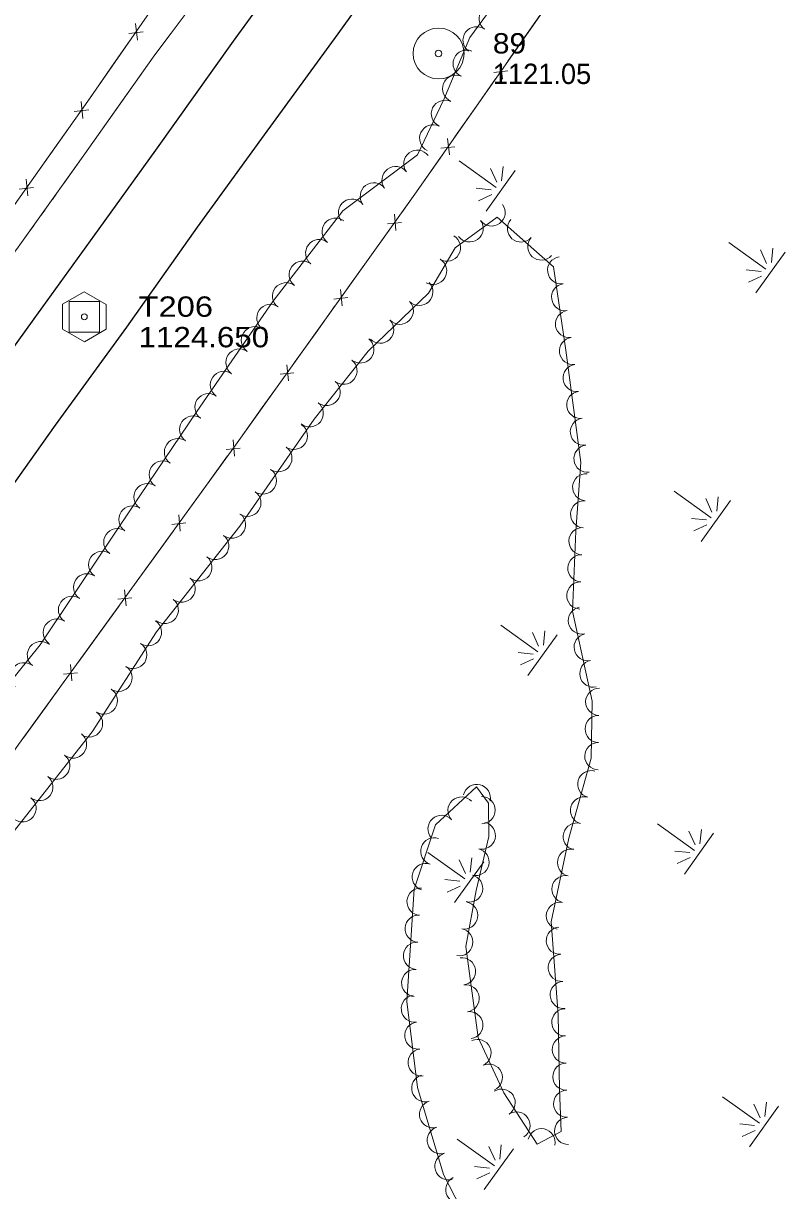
# Model space of a CAD drawing. Extents: x 297327 to 299792, y 46897 to 49095.
# Drawn here: x 298564.4 to 298789.7, y 47500 to 47844.1 of the extents above; entities that cross this region are included whole.
import ezdxf

# ---------------------------------------------------------------- set-up
doc = ezdxf.new("R2010")
doc.units = 0
doc.header["$LTSCALE"] = 2.4
for name, color, linetype, lineweight in [('11', 7, 'Continuous', 25), ('15', 7, 'Continuous', 13), ('18', 7, 'Continuous', 13), ('19', 7, 'Continuous', 13), ('5', 7, 'Continuous', 13), ('6', 7, 'Continuous', 13)]:
    doc.layers.add(name, color=color, linetype=linetype, lineweight=lineweight)

msp = doc.modelspace()

# ---------------------------------------------------------------- linework, layer by layer
at = {"layer": '11'}
for points in [[(298388.911, 47508.371), (298406.106, 47532.273), (298427.668, 47562.116), (298449.984, 47593.336), (298470.117, 47621.114), (298489.839, 47648.885), (298509.891, 47677.16), (298529.03, 47703.573), (298549.632, 47732.257), (298567.565, 47756.994), (298586.721, 47783.539), (298603.426, 47806.737), (298626.295, 47838.881), (298646.065, 47866.048), (298669.869, 47899.268), (298693.507, 47931.962), (298714.623, 47961.338), (298735.651, 47990.506), (298754.046, 48016.186), (298773.947, 48043.937), (298797.872, 48077.411)], [(298407.334, 47494.128), (298425.338, 47519.051), (298445.675, 47547.22), (298466.267, 47575.884), (298487.159, 47604.501), (298507.887, 47633.716), (298528.686, 47661.791), (298551.246, 47693.855), (298573.871, 47725.614), (298594.877, 47754.505), (298615.749, 47784.013), (298635.436, 47811.25), (298657.227, 47840.959), (298677.914, 47869.928), (298700.338, 47901.145), (298719.301, 47927.484), (298741.917, 47959.101), (298761.856, 47986.895), (298781.415, 48014.255), (298799.539, 48039.023)]]:
    msp.add_lwpolyline(points, dxfattribs=at)
at = {"layer": '15'}
for p, q in [((298713.623, 47842.044), (298719.209, 47850.028)), ((298595.434, 47841.121), (298599.664, 47841.611)), ((298598.015, 47839.119), (298597.473, 47844.055)), ((298707.271, 47832.965), (298713.623, 47842.044)), ((298590.185, 47830.923), (298595.91, 47839.159)), ((298583.675, 47821.559), (298590.185, 47830.923)), ((298705.624, 47827.642), (298705.112, 47832.44)), ((298697.992, 47819.703), (298703.578, 47827.687)), ((298703.122, 47829.595), (298707.233, 47830.058)), ((298581.957, 47816.082), (298581.463, 47821.024)), ((298579.395, 47818.11), (298583.63, 47818.558)), ((298691.64, 47810.624), (298697.992, 47819.703)), ((298574.048, 47807.963), (298579.852, 47816.143)), ((298689.993, 47805.301), (298689.481, 47810.099)), ((298567.448, 47798.662), (298574.048, 47807.963)), ((298687.491, 47807.254), (298691.602, 47807.717)), ((298682.361, 47797.362), (298687.948, 47805.346)), ((298565.716, 47793.194), (298565.222, 47798.136)), ((298563.155, 47795.222), (298567.39, 47795.671)), ((298674.252, 47783.016), (298673.789, 47787.819)), ((298666.54, 47775.155), (298672.207, 47783.082)), ((298671.77, 47784.995), (298675.886, 47785.416)), ((298660.096, 47766.142), (298666.54, 47775.155)), ((298658.394, 47760.836), (298657.931, 47765.639)), ((298655.912, 47762.815), (298660.028, 47763.236)), ((298650.682, 47752.975), (298656.349, 47760.902)), ((298644.238, 47743.962), (298650.682, 47752.975)), ((298642.536, 47738.655), (298642.073, 47743.458)), ((298634.824, 47730.795), (298640.491, 47738.722)), ((298640.054, 47740.634), (298644.17, 47741.055)), ((298628.38, 47721.782), (298634.824, 47730.795)), ((298626.657, 47716.476), (298626.225, 47721.282)), ((298624.188, 47718.471), (298628.307, 47718.866)), ((298618.896, 47708.664), (298624.613, 47716.556)), ((298612.395, 47699.692), (298618.896, 47708.664)), ((298608.191, 47696.391), (298612.309, 47696.786)), ((298610.66, 47694.396), (298610.227, 47699.202)), ((298602.898, 47686.584), (298608.616, 47694.475)), ((298596.398, 47677.612), (298602.898, 47686.584)), ((298594.663, 47672.316), (298594.23, 47677.122)), ((298586.901, 47664.504), (298592.618, 47672.395)), ((298592.193, 47674.311), (298596.312, 47674.706)), ((298580.401, 47655.532), (298586.901, 47664.504)), ((298576.196, 47652.231), (298580.315, 47652.626)), ((298578.665, 47650.236), (298578.233, 47655.042)), ((298570.904, 47642.424), (298576.621, 47650.315)), ((298564.403, 47633.452), (298570.904, 47642.424))]:
    msp.add_line(p, q, dxfattribs=at)
for points in [[(298401.584, 47586.723), (298448.177, 47641.585), (298499.253, 47707.169), (298540.716, 47760.989), (298582.688, 47820.139), (298614.369, 47865.714), (298666.991, 47942.604), (298701.551, 47994.305), (298740.687, 48054.857), (298758.699, 48081.865), (298762.651, 48090.8), (298770.821, 48171.221)], [(298443.923, 47465.07), (298477.895, 47511.728), (298522.34, 47573.628), (298562.948, 47631.443), (298626.887, 47719.694), (298679.84, 47793.758), (298726.071, 47859.836), (298761.348, 47908.474)], [(298675.954, 47788.323), (298679.84, 47793.758), (298682.361, 47797.362)]]:
    msp.add_lwpolyline(points, dxfattribs=at)
at = {"layer": '18'}
for points in [[(298719.368, 47871.608), (298696.039, 47839.957), (298688.394, 47821.676), (298680.555, 47805.336), (298658.55, 47788.85), (298637.979, 47762.048), (298615.485, 47729.631), (298598.69, 47704.808), (298569.292, 47660.886), (298549.381, 47636.177)], [(298556.506, 47599.639), (298584.636, 47635.187), (298603.65, 47664.651), (298628.23, 47695.868), (298650.098, 47727.362), (298666.016, 47747.42), (298683.804, 47764.566), (298691.685, 47777.925), (298704.127, 47786.973), (298720.677, 47772.317), (298724.316, 47747.748), (298728.759, 47714.572), (298727.272, 47694.382), (298726.322, 47670.821), (298732.072, 47644.291), (298731.799, 47627.438), (298725.25, 47603.865), (298720.052, 47579.21), (298722.044, 47551.803), (298722.477, 47529.92), (298722.927, 47517.394), (298715.867, 47513.676), (298706.006, 47528.837), (298698.504, 47545.108), (298694.811, 47571.896), (298697.857, 47588.405), (298701.652, 47604.341), (298701.57, 47614.18), (298698.039, 47619.002), (298685.929, 47607.838), (298679.626, 47588.809), (298677.438, 47555.722), (298680.627, 47530.368), (298688.247, 47504.735), (298696.782, 47488.144)]]:
    msp.add_lwpolyline(points, dxfattribs=at)
for centre, start, end in [((298702.764, 47845.549), 53.61485, 233.59953), ((298698.013, 47839.103), 53.61485, 233.59953), ((298695.07, 47832.208), 67.31328, 247.29796), ((298691.981, 47824.82), 67.31328, 247.29796), ((298688.673, 47817.413), 64.37863, 244.36331), ((298685.21, 47810.194), 64.37863, 244.36331), ((298680.52, 47802.691), 36.84797, 216.83265), ((298674.112, 47797.89), 36.84797, 216.83265), ((298667.703, 47793.089), 36.84797, 216.83265), ((298661.295, 47788.288), 36.84797, 216.83265), ((298702.446, 47788.342), 216.03284, 36.01752), ((298656.47, 47782.697), 52.5008, 232.48548), ((298695.97, 47783.632), 216.03284, 36.01752), ((298711.096, 47783.601), 138.48088, 318.46556), ((298651.594, 47776.345), 52.5008, 232.48548), ((298689.278, 47777.969), 239.46963, 59.45431), ((298717.09, 47778.292), 138.48088, 318.46556), ((298646.719, 47769.993), 52.5008, 232.48548), ((298685.209, 47771.073), 239.46963, 59.45431), ((298722.949, 47771.278), 98.43269, 278.41736), ((298641.844, 47763.641), 52.5008, 232.48548), ((298681.134, 47764.903), 223.95482, 43.9395), ((298724.123, 47763.357), 98.43269, 278.41736), ((298675.369, 47759.346), 223.95482, 43.9395), ((298637.198, 47757.247), 55.25107, 235.23574), ((298725.296, 47755.436), 98.43269, 278.41736), ((298669.604, 47753.789), 223.95482, 43.9395), ((298632.633, 47750.668), 55.25107, 235.23574), ((298628.068, 47744.089), 55.25107, 235.23574), ((298663.75, 47747.936), 231.5722, 51.55687), ((298726.466, 47747.486), 97.63545, 277.62013), ((298658.773, 47741.664), 231.5722, 51.55687), ((298623.504, 47737.511), 55.25107, 235.23574), ((298727.528, 47739.549), 97.63545, 277.62013), ((298653.795, 47735.392), 231.5722, 51.55687), ((298618.939, 47730.932), 55.25107, 235.23574), ((298728.591, 47731.613), 97.63545, 277.62013), ((298648.817, 47729.12), 231.5722, 51.55687), ((298614.436, 47724.341), 55.92576, 235.91044), ((298729.654, 47723.677), 97.63545, 277.62013), ((298644.141, 47722.457), 235.23331, 55.21799), ((298609.949, 47717.709), 55.92576, 235.91044), ((298639.574, 47715.88), 235.23331, 55.21799), ((298730.717, 47715.74), 97.63545, 277.62013), ((298605.462, 47711.077), 55.92576, 235.91044), ((298635.007, 47709.303), 235.23331, 55.21799), ((298730.327, 47707.328), 85.79541, 265.78009), ((298600.975, 47704.445), 55.92576, 235.91044), ((298630.44, 47702.726), 235.23331, 55.21799), ((298729.739, 47699.342), 85.79541, 265.78009), ((298596.523, 47697.802), 56.21236, 236.19704), ((298625.894, 47696.289), 231.79107, 51.77574), ((298592.069, 47691.148), 56.21236, 236.19704), ((298620.941, 47689.998), 231.79107, 51.77574), ((298729.25, 47691.421), 87.6987, 267.68338), ((298587.615, 47684.494), 56.21236, 236.19704), ((298615.987, 47683.707), 231.79107, 51.77574), ((298728.927, 47683.42), 87.6987, 267.68338), ((298583.161, 47677.84), 56.21236, 236.19704), ((298611.034, 47677.416), 231.79107, 51.77574), ((298728.605, 47675.419), 87.6987, 267.68338), ((298578.707, 47671.185), 56.21236, 236.19704), ((298606.08, 47671.125), 231.79107, 51.77574), ((298729.074, 47668.02), 102.23657, 282.22124), ((298574.254, 47664.531), 56.21236, 236.19704), ((298601.121, 47664.596), 237.1723, 57.15698), ((298730.77, 47660.194), 102.23657, 282.22124), ((298569.532, 47657.844), 51.14511, 231.12979), ((298596.779, 47657.868), 237.1723, 57.15698), ((298564.508, 47651.609), 51.14511, 231.12979), ((298732.466, 47652.368), 102.23657, 282.22124), ((298592.437, 47651.14), 237.1723, 57.15698), ((298588.095, 47644.413), 237.1723, 57.15698), ((298734.164, 47644.061), 89.07961, 269.06429), ((298583.754, 47637.685), 237.1723, 57.15698), ((298734.035, 47636.054), 89.07961, 269.06429), ((298579.029, 47631.479), 231.65223, 51.63691), ((298733.905, 47628.048), 89.07961, 269.06429), ((298574.06, 47625.2), 231.65223, 51.63691), ((298569.092, 47618.921), 231.65223, 51.63691), ((298731.847, 47619.783), 74.48142, 254.4661), ((298698.089, 47615.734), 346.22181, 166.20649), ((298564.123, 47612.642), 231.65223, 51.63691), ((298693.577, 47612.038), 42.68009, 222.66476), ((298699.491, 47612.125), 270.48516, 90.46984), ((298729.704, 47612.068), 74.48142, 254.4661), ((298687.69, 47606.611), 42.68009, 222.66476), ((298699.566, 47604.627), 256.61273, 76.59741), ((298727.561, 47604.353), 74.48142, 254.4661), ((298685.546, 47600.017), 71.68117, 251.66585), ((298697.711, 47596.837), 256.61273, 76.59741), ((298725.873, 47596.663), 78.10237, 258.08705), ((298683.029, 47592.416), 71.68117, 251.66585), ((298695.856, 47589.048), 256.61273, 76.59741), ((298724.221, 47588.828), 78.10237, 258.08705), ((298681.485, 47585.165), 86.22428, 266.20895), ((298694.373, 47581.07), 259.55384, 79.53852), ((298722.57, 47580.993), 78.10237, 258.08705), ((298680.957, 47577.176), 86.22428, 266.20895), ((298692.92, 47573.196), 259.55384, 79.53852), ((298722.559, 47573.633), 94.16473, 274.14941), ((298680.429, 47569.186), 86.22428, 266.20895), ((298723.139, 47565.647), 94.16473, 274.14941), ((298693.701, 47564.604), 277.85699, 97.84167), ((298679.9, 47561.196), 86.22428, 266.20895), ((298694.794, 47556.672), 277.85699, 97.84167), ((298723.719, 47557.661), 94.16473, 274.14941), ((298679.815, 47553.619), 97.17662, 277.1613), ((298695.888, 47548.74), 277.85699, 97.84167), ((298724.185, 47549.559), 91.14123, 271.12591), ((298680.814, 47545.675), 97.17662, 277.1613), ((298724.343, 47541.553), 91.14123, 271.12591), ((298681.813, 47537.73), 97.17662, 277.1613), ((298698.298, 47540.55), 294.76047, 114.74514), ((298701.65, 47533.279), 294.76047, 114.74514), ((298724.501, 47533.548), 91.14123, 271.12591), ((298682.878, 47530.15), 106.56346, 286.54813), ((298705.421, 47525.892), 303.0484, 123.03307), ((298724.73, 47525.578), 92.06514, 272.04982), ((298685.16, 47522.475), 106.56346, 286.54813), ((298709.787, 47519.18), 303.0484, 123.03307), ((298725.018, 47517.576), 92.06514, 272.04982), ((298687.442, 47514.799), 106.56346, 286.54813), ((298717.147, 47514.242), 347.78025, 167.76493), ((298689.723, 47507.124), 106.56346, 286.54813), ((298692.918, 47500.236), 117.23056, 297.21524)]:
    msp.add_arc(centre, 4.004, start, end, dxfattribs=at)
at = {"layer": '19'}
for p, q in [((298692.862, 47803.505), (298703.775, 47795.695)), ((298700.795, 47788.697), (298709.406, 47800.728)), ((298703.981, 47797.306), (298702.13, 47801.336)), ((298705.826, 47801.869), (298705.381, 47797.656)), ((298572.946, 47792.164), (298574.037, 47793.693)), ((298702.348, 47795.025), (298697.937, 47795.477)), ((298698.624, 47791.806), (298702.468, 47793.586)), ((298569.67, 47787.577), (298570.762, 47789.106)), ((298566.395, 47782.99), (298567.486, 47784.519)), ((298772.438, 47779.449), (298783.351, 47771.639)), ((298780.371, 47764.641), (298788.982, 47776.672)), ((298783.557, 47773.25), (298781.706, 47777.28)), ((298785.402, 47777.813), (298784.957, 47773.6)), ((298781.924, 47770.969), (298777.513, 47771.421)), ((298778.2, 47767.75), (298782.044, 47769.53)), ((298756.308, 47706.161), (298767.221, 47698.351)), ((298764.241, 47691.353), (298772.852, 47703.384)), ((298767.427, 47699.962), (298765.576, 47703.992)), ((298769.272, 47704.525), (298768.827, 47700.312)), ((298765.794, 47697.681), (298761.383, 47698.133)), ((298762.07, 47694.462), (298765.914, 47696.242)), ((298705.199, 47666.629), (298716.112, 47658.819)), ((298713.132, 47651.821), (298721.743, 47663.852)), ((298716.318, 47660.43), (298714.467, 47664.46)), ((298718.163, 47664.993), (298717.718, 47660.78)), ((298714.685, 47658.149), (298710.274, 47658.601)), ((298710.961, 47654.93), (298714.805, 47656.71)), ((298751.377, 47608.094), (298762.29, 47600.284)), ((298759.31, 47593.286), (298767.921, 47605.317)), ((298762.496, 47601.895), (298760.645, 47605.925)), ((298764.341, 47606.458), (298763.896, 47602.245)), ((298760.863, 47599.614), (298756.452, 47600.066)), ((298683.616, 47599.683), (298694.529, 47591.873)), ((298691.549, 47584.875), (298700.16, 47596.906)), ((298694.735, 47593.484), (298692.884, 47597.514)), ((298696.58, 47598.047), (298696.135, 47593.834)), ((298757.139, 47596.395), (298760.983, 47598.175)), ((298693.102, 47591.203), (298688.691, 47591.655)), ((298689.378, 47587.984), (298693.222, 47589.764)), ((298770.525, 47527.634), (298781.438, 47519.824)), ((298778.458, 47512.826), (298787.069, 47524.857)), ((298781.644, 47521.435), (298779.793, 47525.465)), ((298783.489, 47525.998), (298783.044, 47521.785)), ((298780.011, 47519.154), (298775.6, 47519.606)), ((298776.287, 47515.935), (298780.131, 47517.715)), ((298692.341, 47515.106), (298703.254, 47507.296)), ((298700.274, 47500.298), (298708.885, 47512.329)), ((298703.46, 47508.907), (298701.609, 47512.937)), ((298705.305, 47513.47), (298704.86, 47509.257)), ((298701.827, 47506.626), (298697.416, 47507.078)), ((298698.103, 47503.407), (298701.947, 47505.187))]:
    msp.add_line(p, q, dxfattribs=at)
for points in [[(298503.742, 47697.478), (298514.812, 47710.941), (298526.649, 47726.155), (298534.399, 47737.656), (298546.205, 47756.567), (298562.394, 47777.388), (298582.54, 47805.6), (298602.679, 47834.157), (298623.553, 47862.124), (298639.747, 47887.514), (298653.06, 47906.486), (298670.901, 47932.218), (298687.983, 47957.11), (298704.974, 47979.962), (298727.406, 48011.113), (298744.717, 48035.236), (298760.985, 48057.025), (298778.27, 48079.067), (298801.383, 48109.85), (298823.913, 48141.926), (298836.751, 48159.996), (298848.108, 48178.546), (298852.756, 48186.566)], [(298591.974, 47818.978), (298602.679, 47834.157), (298607.864, 47841.104)], [(298576.221, 47796.751), (298582.54, 47805.6), (298591.974, 47818.978)]]:
    msp.add_lwpolyline(points, dxfattribs=at)
at = {"layer": '5'}
for points in [[(298575.936, 47761.343), (298575.936, 47753.952), (298582.396, 47750.225), (298588.793, 47753.89), (298588.793, 47761.219), (298582.271, 47764.945)], [(298577.85, 47753.08), (298577.85, 47762.08), (298586.85, 47762.08), (298586.85, 47753.08)]]:
    msp.add_lwpolyline(points, close=True, dxfattribs=at)
msp.add_circle((298582.35, 47757.58), 0.871, dxfattribs=at)
at = {"layer": '6'}
for radius in [7.5, 0.96]:
    msp.add_circle((298686.813, 47835.201), radius, dxfattribs=at)

# ---------------------------------------------------------------- texts
at = {"layer": '5'}
for s, width, p in [('T206', 1.2, (298598.35, 47757.58)), ('1124.650', 1.15, (298598.35, 47748.58))]:
    msp.add_text(s, height=6, dxfattribs=dict(at, width=width)).set_placement(p)
at = {"layer": '6', "width": 1.1}
msp.add_text('89', height=6, dxfattribs=at).set_placement((298702.813, 47835.201))
at = {"layer": '6'}
msp.add_text('1121.05', height=6, dxfattribs=at).set_placement((298702.813, 47826.201))

doc.saveas('drawing.dxf')
